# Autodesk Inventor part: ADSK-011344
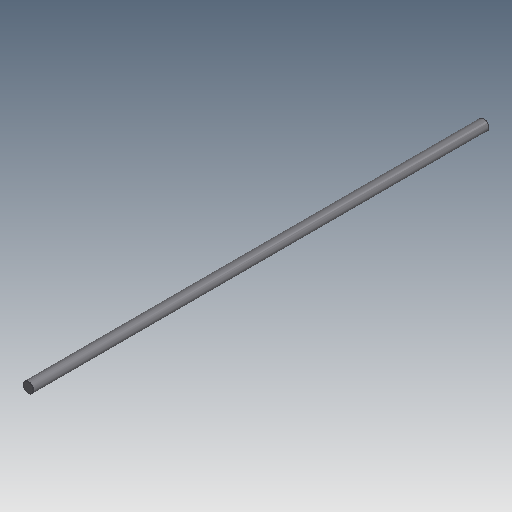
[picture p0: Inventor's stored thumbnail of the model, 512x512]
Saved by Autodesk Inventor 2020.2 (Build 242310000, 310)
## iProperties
Created: 1999-11
Part Number: ADSK-011344
Material: Pearson Hardened Shafting
Document SubType Name: Modeling
Designer: glanglot
Density: 7.83 g/cm^3
Appearance: Metal-Steel(Polish)
Mass: 4318.9 g
Surface Area: 894.894 cm^2
Volume: 551.584 cm^3
Control State: 0
Master: False
Checked Out: False
Shininess: 60.0
Length Units: 11272
Angle Units: 11279
Time Units: 11290
Mass Units: 11286
Length Display Precision: 3
Angle Display Precision: 2
Compacted: True
Cutlength: 43
Material Desc: ROUND,CASE HRDN,1.000DIA
Material_Number: A084598
Dimensions: 1x43x1 in
Mass: 9,522 lb
VLT_Material: Pearson Hardened Shafting
Density: 7.83
Volumn: 551.587613144078
Area: 894.8960813654454
PropertySet Name: Model Information
Author: glanglot
Revision Number: -
Title: ADSK-011344
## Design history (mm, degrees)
node "Extrusion1" dims "d1" = 1092.2, "d2" = 0
workplane "Work Plane1"
node "Hole1" dims "d5" = 4.9784, "d6" = 9.525, "d7" = 6.35, "d8" = 60 deg, "d9" = 12.7, "d10" = 118 deg
workaxis "Work Axis1"
node "Rectangular Pattern2" dims "d16" = 70, "d18" = 152.4
node "Chamfer1" dims "d19" = 0.79375, "d20" = 0.79375, "d22" = 45 deg
node "Solide1"
node "Corps solides"
node "Corps surfaciques"
sketch "Sketch1"
  geometry: C1 r 12.7 at (0, 0); 1 further point
  constraints: 1 centre point, 1 coincident
  dimensions: "d0" = 25.4 diameter of C1
sketch "Sketch2"
  geometry: L1 (12.7, -546.1)-(-12.7, -546.1) reference; L2 (-12.7, 546.1)-(12.7, 546.1) reference; L3 (12.7, -457.2)-(-12.7, -457.2); L4 (-12.7, -546.1)-(-12.7, 546.1) reference; 1 further point
  constraints: 2 end point, 1 midpoint
  dimensions: "d3" = 88.9 distance between parallel lines of L3 L1; "d21" = 12.7 distance from line of L4 point (0, -457.2) (= 0.5 x d0)
